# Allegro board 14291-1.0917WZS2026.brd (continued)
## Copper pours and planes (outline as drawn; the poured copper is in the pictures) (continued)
3D3V_S5_WLAN on BOTTOM: 167.41,40.5 167.15,40.76 167.15,45.3 167.26,45.41 169.18,45.41 169.62,44.97 169.62,40.72 169.4,40.5
3D3V_S5_WLAN on L4: 167.62,65.13 169.07,65.13 169.5,64.7 169.5,60.42 170.63,59.29 170.63,40.85 169.92,40.14 167.71,40.14 167.33,40.52 167.33,41.46 167.86,41.99 167.86,51.54 166.82,52.59 166.82,62.2 167.38,62.76 167.38,64.89
3D3V_TPM on BOTTOM: 167.8,18.62 167.63,18.8 167.63,19.33 168.04,19.74 168.04,20.99 168.16,21.11 169.23,21.11 169.52,21.4 172.66,21.4 172.8,21.26 172.8,20.81 172.66,20.68 171.5,20.68 171.35,20.52 171.35,19.68 170.66,19 168.9,19 168.53,18.62 ; 7 cut-outs
3D3V_TPM_1 on BOTTOM: 162.05,31.68 160.7,31.68 160.6,31.58 160.6,29.39 160.61,29.38 160.6,29.37 160.6,29.04 160.68,28.96 162.4,28.96 162.5,29.06 162.5,29.93 162.71,30.13 162.71,31.02
3D3V_VGA_S0 on TOP: 197.86,137.95 197.68,138.14 197.68,139.92 197.81,140.05 198.33,140.05 198.46,139.92 198.46,138.84 198.57,138.84 198.8,138.61 200.53,138.61 201.4,139.48 202.56,139.48 202.65,139.56 202.65,140.92 202.83,141.11 203.45,141.11 204.15,141.81 211.71,141.81 212.92,140.6 212.92,139.91 212.75,139.73 209.44,139.73 208.66,140.52 205.84,140.52 204.49,139.17 203.96,139.17 203.53,138.74 203.07,138.74 202.81,138.49 201.47,138.49 200.93,137.95 ; 4 cut-outs
3D3V_VGA_S0 on BOTTOM: 167.41,127.56 167.23,127.75 167.23,129.36 166.45,130.14 166.45,135.05 163.36,138.13 163.36,144.04 163.79,144.47 163.79,148.11 165.86,150.18 166.99,150.18 168.17,149 168.17,146.46 165.5,143.79 165.5,141.55 166.37,140.68 166.37,138.31 168.05,136.63 168.05,132.58 168.49,132.15 170.55,132.15 170.62,132.08 170.62,128.37 169.82,127.56 ; 2 cut-outs
3D3V_VGA_S0 on BOTTOM: 211.55,139.86 211.42,139.98 211.42,140.52 211.6,140.7 212.01,140.7 212.19,140.87 212.19,142.3 212.01,142.47 211.42,142.47 211.22,142.27 211.22,141.81 211.13,141.72 209.95,141.72 209.78,141.89 209.78,142.51 209.64,142.65 208.94,142.65 208.83,142.76 208.83,143.15 208.96,143.28 209.91,143.28 210.88,144.25 210.88,150.21 218.34,157.66 218.34,172.9 215,176.25 215,177.47 215.29,177.77 217.25,177.77 219.51,175.52 219.51,156.55 212.55,149.59 212.55,144.42 213.47,143.5 213.47,143.15 213.48,143.15 213.48,140.56 212.78,139.86 ; 4 cut-outs
3D3V_VGA_S0 on L3: 217.06,178.46 217.06,176.7 216.75,176.39 193.79,176.39 193.45,176.74 183.75,176.74 180.89,173.88 170.47,173.88 167.06,170.47 167.06,148.82 166.63,148.4 165.51,148.4 164.63,149.28 164.63,159.42 165.65,160.44 165.65,163.9 164.81,164.74 164.81,173.94 168.52,177.65 168.52,179.03 169.19,179.7 186.44,179.7 187.43,178.72 216.8,178.72
81208_AGND on BOTTOM: 115.98,140.78 115.55,141.22 114.32,141.22 114.32,141.22 110.68,141.22 110.46,141 110.05,141 110,141.05 110,141.48 110.08,141.56 110.48,141.56 110.76,141.84 110.76,141.84 110.85,141.93 111.25,141.93 111.41,142.09 111.41,145.16 111.59,145.34 116.2,145.34 116.38,145.53 117.08,145.53 117.15,145.45 117.15,144.98 116.99,144.82 116.99,143.43 116.93,143.37 116.77,143.37 116.63,143.22 116.63,141.74 117.01,141.36 117.22,141.36 117.29,141.28 117.29,140.82 117.25,140.78 116.47,140.78 116.46,140.78 ; 18 cut-outs
+0D675V_DDR_P on TOP: 44.47,21.54 44,22.01 43.58,22.01 43.52,21.94 41.25,21.94 40.92,22.27 40.92,23.82 40.99,23.89 44.27,23.89 45.03,24.66 46.11,24.66 46.73,24.03 46.73,23.02 46.68,22.97 45.86,22.97 45.86,23.18 45.66,23.18 45.53,23.3 44.98,23.3 44.7,23.02 44.7,22.64 44.98,22.36 46.73,22.36 46.73,22.17 45.25,22.17 44.61,21.54 ; 3 cut-outs
+DC_IN on TOP: 85.47,152.17 85.47,153.07 84.81,153.73 84.81,158.61 85.61,159.4 85.61,162.35 85.97,162.72 89.55,162.72 89.85,162.42 89.85,161.11 90.8,160.16 90.8,157.61 91.04,157.37 91.9,157.37 93.52,158.98 96.35,158.98 96.68,159.31 97.17,159.31 97.24,159.24 97.24,158.72 96.88,158.36 96.87,158.36 96.87,155.78 96.85,155.76 95.27,155.76 95.09,155.58 95.09,155.05 94.18,154.13 93.04,154.13 92.93,154.03 92.93,152.52 92.45,152.04 85.6,152.04 ; 1 cut-out
+DC_IN on BOTTOM: 88.95,151.89 88.71,152.12 88.71,154.97 88.11,155.58 88.11,156.75 88.87,157.51 90.46,157.51 91.19,158.25 91.19,159.31 91.35,159.47 94.68,159.47 95.77,158.38 95.77,155.59 96.01,155.35 96.01,153.17 95.52,152.68 93.19,152.68 92.41,151.89 ; 5 cut-outs
+DC_IN on L3: 88.54,152.43 91.23,152.43 92.45,153.65 94.66,153.65 95.24,154.23 95.24,158.81 94.48,159.57 89.15,159.57 87.29,157.71 87.29,153.67
+PWR_SRC_1D35V on TOP: 53.97,22.89 53.72,23.14 53.72,24.79 53.08,25.43 53.08,26.57 53.21,26.7 60.07,26.7 60.32,26.45 60.32,23.02 60.19,22.89 ; 2 cut-outs
+PWR_SRC_1D35V on BOTTOM: 52.61,22.89 52.17,23.34 52.17,26.86 52.31,27.01 56.86,27.01 57.73,26.14 57.73,22.99 57.63,22.89
+SDC_IN on TOP: 100.71,152.35 100.71,149.86 100.88,149.69 101.44,149.69 102.48,148.65 104.16,148.65 105,149.48 105,153.67 104.95,153.73 104.13,153.73 103.93,153.93 103.93,154.79 103.68,155.05 102.38,155.05 102.28,154.94 102.28,152.71 101.93,152.35
AD+ on TOP: 101.98,159.8 97.81,159.8 97.45,159.43 97.45,158.58 97.18,158.31 97.18,150.09 97.51,149.76 100.1,149.76 100.32,149.99 100.32,154.46 102.26,156.39 105.13,156.39 105.33,156.6 105.33,157.03 105.23,157.13 101.87,157.13 101.09,156.34 100.6,156.34 100.32,156.62 100.32,158.2 100.58,158.45 101.87,158.45 102.15,158.73 102.15,159.62
AUD_AGND on TOP: 23.25,9.05 23.08,9.21 23.08,9.38 22.91,9.55 21.9,9.55 21.74,9.72 21.74,10.49 21.86,10.61 22.96,10.61 23.06,10.71 23.06,11.33 23.19,11.46 23.97,11.46 24.34,11.1 24.34,10.38 24.12,10.16 24.12,9.15 24.02,9.05 ; 3 cut-outs
AUD_AGND on TOP: 28.09,23.15 28.04,23.2 28.04,23.43 27.62,23.86 26.02,23.86 25.65,23.49 24.94,23.49 24.81,23.49 24.71,23.59 24.71,24.02 24.54,24.19 24,24.19 23.81,24.38 23.81,25.56 24.17,25.91 28.82,25.91 29,25.73 29,23.88 28.73,23.61 28.73,23.22 28.66,23.15 ; 5 cut-outs
AUD_AGND on TOP: 19.86,16.77 19.81,16.82 19.81,18.62 19.17,19.26 18.13,19.26 18.05,19.33 18.05,20.22 18.36,20.53 18.36,21.37 18.41,21.42 19.07,21.42 19.2,21.54 19.2,21.95 19.35,22.1 20.49,22.1 20.85,21.75 22.48,21.75 22.73,21.5 22.73,20.91 22.61,20.79 21.7,20.79 21.31,21.19 20.11,21.19 19.96,21.04 19.96,20.22 20.06,20.12 20.54,20.12 20.72,19.94 20.72,16.9 20.59,16.77 ; 3 cut-outs
AUD_AGND on BOTTOM: 27.84,23.89 27.59,24.14 27.59,24.78 27.11,25.25 25.48,25.25 24.34,24.1 23.88,24.1 23.65,24.34 23.65,26.25 24.35,26.96 29.62,26.96 29.81,26.77 29.81,24.39 29.31,23.89 ; 3 cut-outs
AUD_AGND on L2VCC: outline of 84 points within 0.76,1.23 30.64,25.95
AUD_AGND on L5GND: outline of 84 points within 0.76,1.23 30.64,25.95
AUD_SPK_L+ on TOP: 39.3,13.14 39.18,13.27 39.18,14.47 39.37,14.66 39.67,14.66 40.05,14.28 40.81,14.28 40.88,14.34 41.71,14.34 41.75,14.3 41.75,13.4 41.68,13.32 39.79,13.32 39.61,13.14 ; 2 cut-outs
AUD_SPK_L+_C on TOP: 43.58,11.35 42.88,12.05 42.88,12.88 42.25,13.51 42.25,14.29 42.29,14.33 43.24,14.33 44.08,13.49 44.08,12.73 44.45,12.37 46.12,12.37 46.2,12.29 46.2,11.41 46.14,11.35 ; 1 cut-out
AUD_SPK_L+_C on TOP: 63.19,10.75 63.11,10.83 63.11,11.74 63.16,11.78 64.25,11.78 64.36,11.66 71.59,11.66 71.63,11.63 71.63,10.95 71.55,10.88 64.36,10.88 64.24,10.75
AUD_SPK_L- on TOP: 40.26,11.06 39.66,11.66 39.39,11.66 39.26,11.79 39.26,12.64 39.7,13.08 40.87,13.08 40.89,13.06 40.89,11.94 40.86,11.92 40.86,11.17 40.75,11.06 ; 1 cut-out
AUD_SPK_L-_C on TOP: 63.16,9.48 63.11,9.54 63.11,10.47 63.16,10.52 64.62,10.52 64.76,10.66 71.52,10.66 71.59,10.59 71.59,9.96 71.5,9.88 65.11,9.88 64.72,9.48
AUD_SPK_L-_C on TOP: 41.98,10.08 41.4,10.66 41.4,13.06 41.55,13.21 42.32,13.21 42.45,13.08 42.45,11.24 42.59,11.1 46.19,11.1 46.21,11.08 46.21,10.11 46.18,10.08
AUD_SPK_R+ on TOP: 37.5,8.89 37.26,9.13 37.26,9.82 37.43,9.99 39.73,9.99 39.85,9.87 39.85,8.98 39.77,8.89 ; 2 cut-outs
AUD_SPK_R+_C on TOP: 63.13,8.2 62.99,8.34 62.99,9.02 63.19,9.23 64.82,9.23 65.26,9.66 71.54,9.66 71.59,9.61 71.59,8.97 71.5,8.88 65.65,8.88 64.98,8.2
AUD_SPK_R+_C on TOP: 42.78,8.63 42.53,8.87 41.98,8.87 41.97,8.86 40.33,8.86 40.25,8.94 40.25,9.82 40.35,9.93 43.54,9.93 43.82,9.65 46.18,9.65 46.24,9.58 46.24,8.66 46.21,8.63
AUD_SPK_R- on TOP: 37.05,7.42 37,7.47 37,8.51 37.26,8.77 39.33,8.77 39.57,8.54 39.57,7.75 39.44,7.62 38.88,7.62 38.35,8.16 37.87,8.16 37.76,8.06 37.76,7.65 37.54,7.42
AUD_SPK_R-_C on TOP: 63.07,6.93 62.9,7.09 62.9,7.85 63,7.95 65.05,7.95 65.77,8.67 71.52,8.67 71.58,8.61 71.58,7.96 71.5,7.88 66.03,7.88 65.08,6.93
AUD_SPK_R-_C on TOP: 41.79,7.31 41.49,7.61 40.18,7.61 40.11,7.67 40.11,8.59 40.17,8.65 42.35,8.65 42.63,8.37 44.68,8.37 44.76,8.3 44.76,7.4 44.66,7.31
BT+ on TOP: 130.93,165.38 130.8,165.51 130.8,167.29 130.17,167.92 130.17,176.18 130.55,176.56 148.71,176.56 149.35,175.92 149.35,173.56 145.74,169.96 138.04,169.96 135,166.91 135,165.51 134.87,165.38 ; 2 cut-outs
BT+ on TOP: 159.76,171.23 159.38,171.61 159.38,177.42 159.18,177.63 159.18,180.98 159.33,181.13 163.82,181.13 164.08,180.88 164.08,178.85 163.29,178.06 163.29,175.57 164.08,174.78 164.08,171.35 163.95,171.23 ; 2 cut-outs
BT+ on BOTTOM: 131.06,167.16 130.17,168.05 130.17,177.07 130.55,177.45 157.86,177.45 159.13,178.72 159.13,180.88 159.38,181.13 163.7,181.13 164.08,180.75 164.08,172.37 161.79,170.08 154.05,170.08 151.94,167.97 143.48,167.97 141.54,169.91 137.39,169.91 134.65,167.16
CHARGER_SRC on TOP: 115.18,156.37 115.06,156.49 115.06,158.91 115.31,159.16 119.88,159.16 120.26,158.78 120.26,156.75 119.88,156.37 ; 2 cut-outs
CHARGER_SRC on BOTTOM: 120.26,155.48 119.88,155.86 114.93,155.86 113.91,156.87 113.91,159.03 114.04,159.16 123.31,159.16 123.44,159.03 123.44,155.73 123.18,155.48 ; 3 cut-outs
CHG_AGND on TOP: 106.17,159.29 105.66,159.8 105.66,162.39 106.49,163.22 107.51,163.22 107.57,163.16 107.57,162.25 107.82,162.01 107.82,159.8 107.31,159.29
CHG_AGND on L3: 106.4,165.51 105.65,164.77 100.42,164.77 100.27,164.62 100.27,156.8 101.47,155.6 102.53,155.6 103.37,156.44 112.59,156.44 112.77,156.62 112.77,157.05 112.31,157.51 109.52,157.51 107.79,159.24 107.79,168.36 108.12,168.69 108.12,170.03 107.89,170.25 106.69,170.25 106.4,169.96
CPVDD on TOP: 20.87,7.27 20.67,7.46 20.67,7.82 21,8.15 21,9.22 21.1,9.33 22.55,9.33 23.11,8.77 23.82,8.77 23.82,8.23 23.79,8.21 22.52,8.21 22.14,7.83 22.14,7.4 22.02,7.27 ; 3 cut-outs
DCBATOUT on TOP: 105.66,153.67 106.78,153.67 106.79,153.67 107.61,153.67 107.94,153.34 108.54,153.34 108.89,152.99 109.77,152.99 109.96,152.8 109.96,152.14 109.86,152.03 109.39,152.03 108.76,151.41 108.76,149.43 108.38,149.05 105.84,149.05 105.56,149.33 105.56,153.57
DCBATOUT on TOP: 138.84,156.22 140.09,156.22 140.36,155.95 140.36,153.6 140.64,153.33 140.64,152.54 140.52,152.42 139.65,152.42 139.26,152.03 137.81,152.03 136.95,152.89 136.95,155 137.1,155.16 137.78,155.16
DCBATOUT on TOP: outline of 102 points within 23.52,26.95 126.61,137.92
DCBATOUT on TOP: 101.34,149.41 99.05,149.41 98.93,149.28 98.93,148.37 99,148.29 101.16,148.29 101.52,148.65 101.52,149.23
DCBATOUT on TOP: 200.1,91.09 198.7,92.49 198.7,95.06 200.18,96.53 200.18,98.77 198.11,100.83 198.11,109.5 198.37,109.76 200.4,109.76 200.65,110.01 200.65,111.28 200.78,111.41 201.54,111.41 201.67,111.28 201.67,105.95 201.92,105.69 202.69,105.69 202.81,105.57 202.81,101.12 204.49,99.45 204.49,97.39 205.63,96.25 212.11,96.25 213.96,98.1 213.96,98.99 215.78,100.81 215.78,105.25 215.91,105.38 216.67,105.38 216.93,105.63 216.93,110.97 217.05,111.09 217.82,111.09 218.21,110.7 220.21,110.7 220.48,110.43 220.48,97.82 220.16,97.16 220.17,95.04 219.61,94.48 214.32,91.09 ; 1 cut-out
DCBATOUT on BOTTOM: 215.91,100.68 215.78,100.81 215.78,105.25 215.91,105.38 216.67,105.38 216.93,105.63 216.93,110.97 217.05,111.09 217.66,111.09 217.75,111 217.75,109.78 218.08,109.45 219.45,109.45 219.72,109.19 219.72,101.31 219.09,100.68 ; 2 cut-outs
DCBATOUT on BOTTOM: 99.35,118.51 99.07,118.79 99.07,135.99 99.5,136.42 99.5,142.18 98.14,143.54 98.14,147.17 98.15,147.18 98.15,148.18 98.66,148.7 98.66,152.37 99.24,152.96 110.4,152.96 112.12,154.68 112.12,155.69 112.53,156.1 114.41,156.1 115.06,155.45 119.71,155.45 120.44,154.72 132.7,154.72 134.33,153.09 136.29,153.09 136.65,153.45 136.65,156.62 136.77,156.75 140.33,156.75 140.71,156.37 140.71,150.14 140.93,149.93 140.93,149.51 142.83,147.6 144.67,147.6 145.66,146.61 145.66,139.6 145.41,139.35 140.96,139.35 140.2,138.59 140.2,135.28 139.95,135.03 137.97,135.03 137.59,135.41 137.59,139.43 136.82,140.19 131.59,140.19 130.94,139.54 130.31,139.54 129.36,138.59 129.36,135.13 128.02,133.79 125.12,133.79 124.07,132.74 124.07,130.71 123.95,130.59 121.91,130.59 121.79,130.71 121.79,136.26 121.53,136.52 119.03,136.52 117.82,135.31 117.82,134.03 117.35,133.55 111.43,133.55 111.07,133.19 111.07,131.23 110.77,130.93 110.77,130.13 110.74,130.1 108.32,130.1 108.13,130.28 108.13,135.52 107.88,135.77 104.1,135.77 103.82,135.49 103.82,119.16 103.17,118.51 ; 9 cut-outs
DCBATOUT on BOTTOM: 198.92,100.2 198.41,100.71 198.41,110.69 198.75,111.03 200.27,111.03 200.65,111.41 201.54,111.41 201.67,111.28 201.67,105.95 201.92,105.69 202.69,105.69 202.81,105.57 202.81,101.12 201.89,100.2 ; 2 cut-outs
DCBATOUT on L2VCC: 201.37,91.28 200.46,92.18 200.46,98.79 198.05,101.2 198.05,109.68 198.19,109.82 200.35,109.82 200.72,110.19 200.72,111.33 200.73,111.35 201.46,111.35 201.73,111.08 201.73,106 202.1,105.63 202.61,105.63 202.75,105.49 202.75,101.04 204.27,99.52 204.27,97.49 205.53,96.23 212.29,96.23 214.05,97.99 214.05,99.14 215.83,100.92 215.83,104.85 216.1,105.12 216.61,105.12 217.1,105.61 217.1,110.31 217.37,110.58 219.75,110.58 219.9,110.44 219.9,95.3 219.79,94.89 213.81,91.28
DCBATOUT on L2VCC: 99.77,118.58 99.37,118.98 99.37,138.25 99.9,138.78 107.87,138.78 108.75,137.89 124.76,137.89 125.74,136.91 125.74,132.93 124.58,131.77 109.11,131.77 107.21,129.87 107.21,120.25 105.54,118.58
DCBATOUT on L3: 200.33,100.59 200.01,100.27 196.77,100.27 192.29,104.75 190.6,104.75 180.38,114.97 180.38,115.71 179.3,116.79 171.3,116.79 155.77,132.31 155.77,138.52 148.55,145.74 139.78,145.74 136.24,149.28 136.24,156.6 136.42,156.78 141.44,156.78 141.55,156.67 141.55,152.57 142.1,152.03 152.22,152.03 164.66,139.58 164.66,138.75 168.04,135.37 168.04,131.19 175.16,124.07 175.16,123.37 176.55,121.98 182.86,121.98 187.09,117.75 188.12,117.75 190.58,115.29 192.75,115.29 195.65,112.39 195.65,107.23 196.23,106.65 198.1,106.65 200.33,104.42
DCBATOUT_+VCCSA on TOP: 135.25,131.98 135.12,132.11 135.12,133.89 135.25,134.01 137.92,134.01 138.1,133.83 138.1,132.21 137.88,131.99 137.58,131.99 137.58,131.98
DCBATOUT_+VCCSA on BOTTOM: 135.38,128.55 135.12,128.81 135.12,134.4 135.38,134.65 139.19,134.65 139.57,134.27 139.57,128.81 139.31,128.55 ; 2 cut-outs
DCBATOUT_CAMERA on TOP: 93.14,153.95 93.14,152.81 93.24,152.71 94.25,152.71 94.61,152.35 94.61,148.67 95.09,148.19 98.24,148.19 98.42,148.37 98.42,149.38 98.29,149.51 96.24,149.51 96.03,149.71 96.03,153.45 95.47,154 93.19,154
DCBATOUT_LCD on TOP: 76.69,176.67 76.56,176.8 76.56,177.34 76.69,177.48 78.54,177.48 78.58,177.43 78.58,176.73 78.52,176.67
DCBATOUT_LCD on BOTTOM: 91.49,150.15 92.28,150.15 94.47,152.34 96.81,152.34 96.87,152.28 96.87,148.85 96.14,148.12 96.14,147.18 95.87,146.91 91.7,146.91 91.33,147.27 91.33,150 ; 1 cut-out
DDR_VREF_S3 on TOP: 43.84,17.6 43.71,17.73 43.71,19.23 43.97,19.49 44.76,19.49 44.87,19.38 44.87,18.93 44.49,18.54 44.49,17.7 44.39,17.6
ECVBAT on TOP: 188.7,59.45 188.59,59.57 188.59,61.06 188.38,61.27 188.36,61.27 187.92,61.72 187.92,62.52 188.05,62.66 188.39,62.66 188.64,62.91 188.64,64.19 188.68,64.23 189.17,64.23 189.26,64.14 189.26,59.64 189.07,59.45
FAN_VCC1 on TOP: 99.03,141.56 98.19,141.56 96.64,140.01 94.81,140.01 94.71,139.91 94.71,137.72 96.49,135.95 96.49,135.13 96.77,134.85 97.33,134.85 97.48,135.01 97.48,138.56 97.89,138.97 98.45,138.97 98.57,139.09 98.57,140.47 98.75,140.64 98.98,140.64 99.11,140.77 99.11,141.48
FB_CAL_PD_VDDQ on TOP: 201.31,149.37 201.18,149.49 201.18,149.83 201.43,150.07 201.72,150.07 201.87,150.23 201.87,150.71 202,150.84 202.48,150.84 202.56,150.76 202.56,149.65 202.28,149.37
FB_CAL_PU_GND on TOP: 202.14,151.08 201.9,151.31 201.9,152.2 201.98,152.28 203.07,152.28 203.39,151.96 203.39,151.29 203.18,151.08 ; 1 cut-out
FB_CAL_TERM_GND on TOP: 204.08,153.09 203.89,153.28 203.89,153.67 204,153.78 204.36,153.78 204.54,153.96 204.54,154.54 204.6,154.6 205.33,154.6 205.43,154.5 205.43,153.55 204.96,153.09 ; 1 cut-out
FBA_PLL_AVDD on TOP: 188.01,143.85 187.9,143.95 187.9,146.01 188.08,146.18 188.08,147.52 188.29,147.73 192.43,147.73 192.68,147.98 192.68,148.32 192.48,148.52 192.22,148.52 192.08,148.67 192.08,149.1 192.19,149.21 194.21,149.21 194.3,149.12 194.3,148.66 194.1,148.47 193.82,148.47 193.59,148.24 193.59,148.04 192.6,147.05 192.26,147.05 191.73,146.51 190.93,146.51 190.47,146.05 189.71,146.05 188.95,145.29 188.95,143.94 188.85,143.85 ; 3 cut-outs
FBA_PLL_AVDD on L3: 192.11,149.39 194.1,149.39 194.2,149.3 194.2,148.6 194.3,148.51 197.04,148.51 197.08,148.55 197.08,148.54 197.48,148.54 197.73,148.8 197.73,149 197.94,149.2 198.26,149.2 198.65,148.82 198.65,146.23 199.28,145.6 199.28,143.74 199.17,143.64 198.6,143.64 198.47,143.77 198.47,144.63 196.19,146.91 194.34,146.91 193.75,147.5 191.99,147.5 191.76,147.73 191.76,148.47 191.96,148.66 191.96,149.24
HDMI_PLL_GND on TOP: 19.07,60.42 19.02,60.46 19.02,68.52 19.73,69.23 19.73,69.24 22.73,69.24 22.88,69.09 22.88,68.23 22.73,68.08 22.12,68.08 21.84,68.36 20.87,68.36 20.87,68.1 20.26,67.49 20.26,60.46 20.22,60.42 ; 2 cut-outs
KB_BL_CTRL# on TOP: 193.94,96.16 193.89,96.21 193.89,97.3 193.99,97.4 194.66,97.4 194.75,97.31 194.75,96.2 194.71,96.16
LCDVDD on BOTTOM: 79.52,157.52 79.43,157.61 79.43,160.4 79.57,160.54 81.26,160.54 81.4,160.4 81.4,157.68 81.24,157.52
LCDVDD_LCD on TOP: 77.66,174.16 77.6,174.23 77.6,175.9 77.67,175.98 78.63,175.98 79.22,176.57 81.46,176.57 81.66,176.37 81.66,175.58 81.5,175.41 79.77,175.41 78.51,174.16
LCDVDD_LCD on BOTTOM: 82.11,158.71 81.87,158.94 81.87,161.19 81.53,161.52 79.84,161.52 79.39,161.97 79.39,175.26 78.99,175.66 78.99,177.12 79.33,177.46 81.37,177.46 82.35,176.49 82.35,168.73 83.91,167.17 83.91,158.92 83.69,158.71 ; 3 cut-outs
M_VREF_CA_DIMMA on TOP: 102.71,27.3 102.44,27.57 102.44,28.83 103.03,29.42 105.32,29.42 105.59,29.14 105.59,27.66 105.23,27.3 ; 3 cut-outs
M_VREF_CA_DIMMA on BOTTOM: 102.71,27.29 102.42,27.59 102.42,27.97 102.92,28.47 102.92,28.48 102.99,28.55 102.99,30.64 103.02,30.66 103.27,30.66 103.3,30.64 103.3,28.94 103.63,28.6 103.63,27.77 103.16,27.29
M_VREF_CA_DIMMB on TOP: 117.05,17.89 116.85,18.08 116.85,19.24 116.67,19.42 116.67,21.29 116.88,21.5 117.42,21.5 117.52,21.39 117.52,19.08 118.13,18.47 118.13,17.99 118.03,17.89
M_VREF_DQ_DIMMA on TOP: 59.2,38.31 58.95,38.56 58.95,39.88 59.54,40.47 59.99,40.47 61.13,39.32 62.55,39.32 62.78,39.08 62.78,38.42 62.67,38.31 ; 3 cut-outs
M_VREF_DQ_DIMMA on TOP: 56.2,45.5 55.88,45.82 55.88,47.09 55.72,47.25 55.23,47.25 55.08,47.4 55.08,47.92 55.21,48.06 56.55,48.06 56.68,47.92 56.68,46.48 56.85,46.31 57.49,46.31 57.58,46.23 57.58,45.6 57.48,45.5 ; 1 cut-out
M_VREF_DQ_DIMMA on BOTTOM: 62.54,37.29 62.07,37.76 62.07,38.85 62.33,39.12 63.33,39.12 63.39,39.06 63.39,37.39 63.29,37.29
M_VREF_DQ_DIMMB on TOP: 77.46,23.53 77.46,23.54 77.12,23.54 77.01,23.65 77.01,26.71 77.21,26.91 77.93,26.91 78.12,26.72 78.12,24.95 78.1,24.94 78.1,23.64 78,23.53 ; 2 cut-outs
M_VREF_DQ_DIMMB on TOP: 58.77,35.47 58.58,35.66 58.58,36.47 58.71,36.6 61.17,36.6 61.24,36.53 61.24,35.62 61.1,35.47
M_VREF_DQ_DIMMB on BOTTOM: 77.09,23.99 76.89,24.19 76.89,25.88 76.62,26.15 76.32,26.15 76.19,26.28 76.19,27.2 76.25,27.26 77.58,27.26 77.92,26.92 77.92,24.11 77.79,23.99
MCT on TOP: 18.66,170.97 18.54,171.1 18.54,173.77 18.79,174.02 21.97,174.02 22.22,173.77 22.22,171.23 21.97,170.97
MIC_GND on BOTTOM: 78.05,164.44 77.84,164.65 77.84,166.16 78.09,166.41 79.01,166.41 79.32,166.1 79.32,164.74 79.02,164.44 ; 1 cut-out
PQ3802_1 on TOP: 104.66,173.25 104.58,173.33 104.58,173.75 104.78,173.95 109.51,173.95 110.85,175.29 113.41,175.29 113.53,175.16 113.53,174.02 113.28,173.77 110.96,173.77 110.44,173.25 ; 2 cut-outs
PS_ID_R1 on TOP: 104.37,175.92 104.18,176.1 104.18,177.28 104.42,177.52 107.13,177.52 107.23,177.41 107.23,176.24 106.91,175.92 ; 2 cut-outs
PS_ID_R2 on TOP: 101.7,172.56 101.61,172.65 101.61,175.42 101.82,175.63 104.6,175.63 104.6,175.63 108.14,175.63 108.26,175.5 108.26,174.52 108.02,174.28 104.54,174.28 104.32,174.06 104.32,173.44 103.44,172.56 ; 4 cut-outs
PSID_DISABLE#_R_C on TOP: 111.78,175.52 111.67,175.63 111.67,176.14 111.51,176.31 108.54,176.31 108.37,176.48 108.37,177.37 108.51,177.52 114.08,177.52 114.55,177.05 114.55,176.14 113.93,175.52 ; 1 cut-out
PWR_1D0V_BOOT on TOP: 146.63,136.95 146.48,137.11 146.48,137.63 146.63,137.78 148.73,137.78 148.81,137.7 148.81,137.09 148.67,136.95
PWR_1D0V_BOOT_R on TOP: 146.7,134.28 146.55,134.43 146.55,136.42 146.63,136.5 148.31,136.5 148.52,136.29 148.52,134.41 148.39,134.28 ; 1 cut-out
PWR_1D0V_LX on TOP: 145.52,133.35 145.31,133.56 145.31,133.59 144.44,134.46 144.44,135.26 144.57,135.4 146.11,135.4 146.21,135.29 146.21,134.15 146.56,133.8 146.56,133.49 146.41,133.35 ; 1 cut-out
PWR_1D0V_LX on BOTTOM: 144.01,130.46 143.76,130.71 143.76,133.25 144.01,133.51 145.66,133.51 145.79,133.63 145.79,134.9 145.92,135.03 146.93,135.03 147.06,134.9 147.06,133.76 147.19,133.63 147.95,133.63 148.08,133.51 148.08,130.59 147.95,130.46
PWR_1D05V_PHASE on BOTTOM: 149.09,153.45 148.46,154.08 147.31,154.08 147.19,154.21 147.19,156.73 147.55,157.1 150.65,157.1 151.25,156.49 151.25,153.57 151.12,153.45
PWR_1D05V_PVDD on BOTTOM: 141.35,154.33 141.22,154.46 141.22,158.65 141.35,158.78 144.52,158.78 144.77,158.53 144.77,156.24 145.03,155.99 145.03,154.72 144.9,154.59 143.38,154.59 142.87,155.1 141.98,155.1 141.85,154.97 141.85,154.46 141.73,154.33 ; 2 cut-outs
PWR_1D35V_DRVH on TOP: 62.42,25.07 61.93,25.56 60.7,25.56 60.7,26.19 60.83,26.32 62.72,26.32 63.46,25.58 63.46,25.22 63.3,25.07
PWR_1D35V_DRVL on TOP: 57.7,17.49 57.53,17.67 57.53,19.46 58.54,19.46 58.67,19.33 58.67,17.66 58.5,17.49
PWR_1D35V_SW on TOP: 60.83,15.9 60.7,16.03 60.7,17.68 60.57,17.81 59.3,17.81 59.05,18.06 59.05,22.25 59.18,22.38 60.45,22.38 60.7,22.64 60.7,25.3 61.88,25.3 62.29,24.89 63.44,24.89 63.62,24.71 63.62,17.17 63.43,16.99 62.04,16.99 61.75,16.7 61.75,16 61.66,15.9
PWR_1D35V_SW on BOTTOM: 60.07,17.05 59.05,18.06 59.05,18.08 58.91,18.22 58.91,24.65 59.13,24.87 63.27,24.87 63.62,24.52 63.62,17.17 63.49,17.05
PWR_1D35V_VTTREF on TOP: 45.09,17.56 45.02,17.63 45.02,19.68 44.89,19.81 44.89,20.69 45.46,21.27 45.46,21.49 45.52,21.55 46.76,21.55 46.76,20.76 45.9,19.9 45.9,19.54 45.89,19.53 45.89,17.66 45.79,17.56
PWR_3D3V_DRVH2 on TOP: 31.01,41.17 30.88,41.3 30.88,43.08 31.01,43.2 31.52,43.2 31.64,43.08 31.64,41.3 31.52,41.17
PWR_3D3V_DRVL2 on TOP: 33.29,45.23 33.17,45.36 33.17,47.14 33.29,47.27 33.8,47.27 33.93,47.14 33.93,45.36 33.8,45.23
PWR_3D3V_LL2 on TOP: 29.76,39.24 27.89,41.1 27.89,42.99 28.1,43.2 30.63,43.2 30.63,41.04 30.75,40.92 31.9,40.92 32.28,41.3 32.28,44.85 32.41,44.98 36.72,44.98 36.85,44.85 36.85,41.46 36.92,41.4 38.61,41.4 38.81,41.19 38.81,40.06 38.67,39.93 32.96,39.93 32.27,39.24
PWR_3D3V_LL2 on BOTTOM: 28.9,40 28.72,40.18 28.72,44.6 29.1,44.98 36.72,44.98 36.85,44.85 36.85,40.76 36.09,40
PWR_5V_DRVH1 on TOP: 48.38,41.18 48.25,41.3 48.25,43.08 48.38,43.21 49.02,43.21 49.14,43.08 49.14,41.43 48.89,41.18
PWR_5V_DRVL1 on TOP: 40.91,45.23 40.79,45.36 40.79,46.25 40.91,46.38 42.18,46.38 42.18,45.36 42.06,45.23
PWR_5V_LL1 on TOP: 39.17,40.15 39.06,40.26 39.06,41.17 39.28,41.38 40.73,41.38 41.04,41.69 41.04,44.73 41.17,44.85 45.23,44.85 45.36,44.73 45.36,43.46 45.61,43.2 47.9,43.2 48.03,43.08 48.03,40.28 47.9,40.15
PWR_5V_LL1 on BOTTOM: 41.9,40.13 41.3,40.74 41.3,44.35 41.68,44.73 47.39,44.73 47.9,44.22 47.9,40.41 47.62,40.13
PWR_+VCCSA on BOTTOM: 133.98,116.62 133.09,117.5 133.09,120.3 133.34,120.55 138.93,120.55 139.31,120.17 139.31,116.74 139.19,116.62
PWR_CHG_HIDRV on BOTTOM: 123.82,155.86 123.69,155.99 123.69,156.62 125.72,156.62 125.85,156.49 125.85,155.99 125.72,155.86
PWR_CHG_LODRV on BOTTOM: 120.52,162.84 120.39,162.97 120.39,163.99 120.52,164.11 121.53,164.11 121.66,163.99 121.66,162.97 121.53,162.84
PWR_CHG_PHASE on BOTTOM: 126.87,156.24 126.23,156.87 123.82,156.87 123.69,157 123.69,159.16 123.44,159.41 122.17,159.41 121.91,159.67 121.91,163.86 122.52,164.47 128.19,164.47 128.9,163.76 128.9,156.62 128.52,156.24
PWR_CHG_PHASE_1 on TOP: 131.19,157.13 130.8,157.51 130.8,164.62 131.06,164.88 134.87,164.88 138.97,160.78 138.97,158.95 137.51,157.49 136.18,157.49 135.82,157.13
PWR_CHG_PHASE_1 on BOTTOM: 131.19,157.13 130.8,157.51 130.8,164.62 131.06,164.88 134.87,164.88 139.31,160.43 139.31,157.38 139.06,157.13
PWR_DCBATOUT_1D0V on BOTTOM: 144.9,136.05 144.52,136.43 140.84,136.43 140.71,136.55 140.71,138.59 141.22,139.09 146.81,139.09 147.01,138.89 147.01,136.12 146.93,136.05
PWR_DCBATOUT_3D3V on TOP: 28.47,43.46 27.81,44.12 27.81,50.4 27.85,50.44 32.02,50.44 32.15,50.31 32.15,43.71 31.9,43.46 ; 2 cut-outs
PWR_DCBATOUT_3D3V on BOTTOM: 28.36,47.14 27.98,47.52 27.98,50.31 28.1,50.44 32.15,50.44 32.28,50.31 32.28,47.39 32.02,47.14
PWR_DCBATOUT_5V on TOP: 45.87,43.46 45.61,43.71 45.61,46.89 45.36,47.14 45.36,51.2 45.74,51.58 49.42,51.58 49.42,43.58 49.3,43.46 ; 2 cut-outs
PWR_DCBATOUT_5V on BOTTOM: 45.87,46.5 45.61,46.76 45.61,47.9 45.36,48.16 45.36,50.06 45.49,50.19 47.14,50.19 48.15,49.17 48.15,46.76 47.9,46.5
PWR_VCCGT_BOOTA on BOTTOM: 112.59,130.1 112.57,130.13 112.57,133.04 112.72,133.19 113.25,133.19 113.46,132.99 113.46,131.45 112.77,130.76 112.77,130.15 112.72,130.1
PWR_VCCGT_GL1 on BOTTOM: 111.48,126.14 111.37,126.24 111.37,126.95 111.42,127 112.72,127 112.77,126.95 112.77,126.22 112.69,126.14
PWR_VCCGT_PHASEDA on BOTTOM: 111.4,130.1 111.37,130.13 111.37,133.01 111.57,133.2 112.14,133.2 112.36,132.98 112.36,130.13 112.34,130.1 112.19,130.1 112.16,130.13 112.16,130.81 112.14,130.84 111.6,130.84 111.55,130.79 111.55,130.13 111.53,130.1
PWR_VCCGT_SWA on BOTTOM: 111.63,122 111.4,122.23 110.36,122.23 110.23,122.1 107.92,122.1 107.69,122.33 107.69,126.7 107.94,126.95 111.12,126.95 111.17,126.9 111.17,126.22 111.5,125.89 112.26,125.89 112.77,125.38 112.77,122.18 112.59,122
PWR_VCCSA_DRVH on BOTTOM: 135.25,127.03 135.12,127.16 135.12,128.05 135.25,128.17 136.39,128.17 136.39,127.03
PWR_VCCSA_DRVL on BOTTOM: 133.47,130.2 133.34,130.33 133.34,132.11 133.47,132.24 133.98,132.24 134.11,132.11 134.11,130.33 133.98,130.2
PWR_VCCSA_SW on BOTTOM: 132.89,123.09 130.8,125.18 130.8,129.7 130.93,129.82 134.49,129.82 134.74,129.57 134.74,127.03 135,126.78 136.52,126.78 136.65,126.9 136.65,128.05 136.77,128.17 138.3,128.17 138.42,128.05 138.42,123.35 138.17,123.09
PWR_VCORE_BOOT on BOTTOM: 125.93,130.61 125.9,130.64 125.9,133.64 126.01,133.75 126.68,133.75 126.79,133.64 126.79,131.91 126.11,131.22 126.11,130.66 126.06,130.61
PWR_VCORE_GL on BOTTOM: 124.81,126.65 124.71,126.75 124.71,127.46 124.76,127.51 126.06,127.51 126.11,127.46 126.11,126.73 126.03,126.65
PWR_VCORE_PHASED on BOTTOM: 124.73,130.61 124.71,130.64 124.71,133.24 125.22,133.75 125.56,133.75 125.7,133.62 125.7,130.64 125.67,130.61 125.52,130.61 125.5,130.64 125.5,131.32 125.47,131.35 124.96,131.35 124.89,131.27 124.89,130.64 124.86,130.61
PWR_VCORE_SW on BOTTOM: 120.98,122.86 120.8,123.04 120.8,127.13 121.13,127.46 124.45,127.46 124.51,127.41 124.51,126.73 124.84,126.39 125.17,126.39 125.56,126 125.56,123.05 125.37,122.86
PWR_VGA_CORE_LGATE1 on TOP: 212.21,105.19 212.08,105.31 212.08,106.84 212.21,106.96 213.1,106.96 213.23,106.84 213.23,105.31 213.1,105.19
PWR_VGA_CORE_LGATE1 on BOTTOM: 212.21,109.88 212.08,110.01 212.08,111.41 212.34,111.66 212.97,111.66 213.23,111.41 213.23,110.01 213.1,109.88
PWR_VGA_CORE_LGATE2 on TOP: 205.61,110.27 205.48,110.39 205.48,111.79 205.61,111.92 206.24,111.92 206.5,111.66 206.5,110.39 206.37,110.27
PWR_VGA_CORE_LGATE2 on BOTTOM: 205.61,105.57 205.48,105.69 205.48,107.09 205.61,107.22 206.37,107.22 206.5,107.09 206.5,105.82 206.24,105.57
PWR_VGA_CORE_PHASE1 on TOP, BOTTOM: 213.61,105.69 213.48,105.82 213.48,111.92 213.1,112.3 209.67,112.3 209.54,112.42 209.54,113.31 212.21,115.98 217.55,115.98 218.56,114.96 218.56,112.3 218.18,111.92 217.29,111.92 216.53,111.15 216.53,105.82 216.4,105.69
PWR_VGA_CORE_PHASE2 on TOP, BOTTOM: 202.18,105.95 202.05,106.07 202.05,111.41 201.67,111.79 201.04,111.79 200.27,112.55 200.27,115.47 200.91,116.11 206.37,116.11 209.29,113.19 209.29,112.3 209.16,112.17 207.77,112.17 207.39,112.55 205.73,112.55 205.23,112.04 205.23,106.33 204.85,105.95
PWR_VGA_CORE_UGATE1 on TOP: 218.31,105.19 218.18,105.31 218.18,106.84 218.31,106.96 219.2,106.96 219.32,106.84 219.32,105.44 219.07,105.19
PWR_VGA_CORE_UGATE1 on BOTTOM: 218.31,109.88 218.18,110.01 218.18,111.54 218.31,111.66 219.07,111.66 219.2,111.54 219.2,110.01 219.07,109.88
PWR_VGA_CORE_UGATE2 on TOP: 199.51,110.27 199.38,110.39 199.38,111.79 199.51,111.92 200.27,111.92 200.4,111.79 200.4,110.39 200.27,110.27
PWR_VGA_CORE_UGATE2 on BOTTOM: 199.51,105.57 199.38,105.69 199.38,107.09 199.51,107.22 200.27,107.22 200.4,107.09 200.4,105.69 200.27,105.57
REGOUT on TOP: 48.2,170.27 48.17,170.3 48.17,171.54 49.29,172.65 50.61,172.65 50.95,172.31 51.48,172.31 51.57,172.22 51.57,171.35 51.43,171.21 50,171.21 49.98,171.2 49.05,170.27 ; 3 cut-outs
RING2 on TOP: 16.56,9.35 15.07,10.84 15.07,11.89 15.22,12.04 16,12.04 16.52,11.52 16.52,10.92 16.8,10.64 17.33,10.64 17.52,10.45 17.52,9.47 17.4,9.35 ; 3 cut-outs
RING2_HPMIC1 on TOP: 16.34,8.02 15.68,8.69 14.25,8.69 14.04,8.9 14.04,9.89 14.16,10.01 15.71,10.01 16.52,9.2 17.6,9.2 17.6,8.15 17.47,8.02 ; 1 cut-out
RTC_AUX_S5 on TOP: 134.44,56.71 134.34,56.81 134.34,58.92 134.54,59.12 136.15,59.12 136.15,59.12 136.35,59.12 136.71,58.75 136.71,56.78 136.64,56.71 ; 2 cut-outs
SD_RCOMP on TOP: 134.69,83.99 134.4,84.28 134.4,84.43 135.77,85.8 139.23,85.8 139.33,85.69 140.23,85.69 140.3,85.63 140.3,85.19 140.22,85.11 136.49,85.11 136.39,85.21 136.18,85.21 134.96,83.99
SLEEVE on BOTTOM: 19.79,9.87 19.62,10.04 19.62,10.37 19.84,10.58 20.54,10.58 20.73,10.77 20.92,10.77 21.08,10.62 21.08,10.5 20.44,9.87
SLEEVE_HPMIC1 on TOP: 18.06,9 17.62,9.43 17.62,11.63 17.81,11.81 19.4,11.81 19.54,11.68 19.54,10.71 19.26,10.42 19.26,9.05 19.21,9 ; 1 cut-out
SM_RCOMP_0 on TOP: 123.08,73.26 123.01,73.33 123.01,73.92 123.82,74.73 123.82,76.22 125.12,77.51 126.33,77.51 126.41,77.43 126.41,77.02 126.34,76.96 125.16,76.96 124.3,76.1 124.3,74.43 123.72,73.84 123.72,73.39 123.59,73.26
SM_RCOMP_1 on TOP: 124.07,73.23 123.97,73.33 123.97,73.99 124.35,74.38 124.35,76.08 125.14,76.86 125.5,76.86 125.57,76.79 125.57,76.38 125.45,76.26 125.12,76.26 124.94,76.08 124.94,74.1 124.66,73.82 124.66,73.33 124.56,73.23
SM_RCOMP_2 on TOP: 124.89,73.26 124.84,73.31 124.84,73.87 125.01,74.05 125.01,75.99 125.18,76.15 125.42,76.15 125.55,76.03 125.55,75.7 125.42,75.57 125.42,74.78 125.47,74.73 125.47,73.33 125.39,73.26
SP_PLLVDD on TOP: 193.34,130.71 193.26,130.79 193.26,131.96 192.93,132.29 192.93,135.74 193.09,135.89 194.15,135.89 194.28,135.77 194.28,133.81 194.03,133.56 194.03,132.41 194.58,131.86 194.99,131.86 195.12,131.73 195.12,130.81 195.02,130.71 ; 4 cut-outs
TP_VDD on TOP: 54.02,69.4 53.8,69.62 53.8,70.85 53.85,70.89 53.85,71.33 53.92,71.4 55.31,71.4 55.42,71.3 55.42,69.44 55.38,69.4
TP_VDD on TOP: 47.72,76.23 47.68,76.27 47.68,76.49 47.13,77.03 47.13,79.96 47.57,80.4 49.61,80.4 49.88,80.13 49.88,78.99 48.65,78.99 48.29,78.64 48.29,76.98 48.1,76.8 48.1,76.39 48.11,76.39 48.11,76.28 48.06,76.23
TPAN_VDD on BOTTOM: 68.74,156.4 67.57,157.58 67.57,158.65 67.77,158.85 73.18,158.85 73.35,158.68 74.34,158.68 74.34,158.68 74.46,158.56 74.46,157.52 74.28,157.34 73.2,157.34 72.26,156.4 ; 1 cut-out
TPAN_VDD_F on BOTTOM: 73.61,159.09 72.33,160.36 69.21,160.36 68.9,160.67 68.9,162.43 70.26,163.78 72.61,163.78 73.59,162.81 73.59,160.55 73.95,160.19 77.02,160.19 77.25,159.96 77.25,159.22 77.11,159.09 ; 1 cut-out
TPS51216_PHS_SET on TOP: 57.8,15.9 57.4,16.3 57.4,17.3 57.45,17.35 59.08,17.35 59.14,17.41 60.08,17.41 60.08,15.9 ; 2 cut-outs
USB20_VCCA on TOP: 183.87,34.42 183.62,34.67 182.59,34.67 181.31,35.96 179.83,35.96 179.59,36.2 179.59,39.67 179.93,40.02 182.17,40.02 183.55,38.65 185.2,38.65 185.83,38.02 187.65,38.02 187.72,37.95 187.72,34.55 187.59,34.42
USB20_VCCA on BOTTOM: 180.21,28.14 179.94,28.41 179.94,28.96 180.05,29.07 180.05,29.06 181.2,29.06 181.76,29.62 182.42,29.62 182.58,29.47 182.58,28.26 182.45,28.14 ; 1 cut-out
USB20_VCCA on BOTTOM: 184.12,37.71 183.86,37.97 180.48,37.97 180.3,38.16 180.3,39.92 180.53,40.15 182.92,40.15 183.73,39.34 183.73,39.33 185.95,39.33 186.17,39.11 186.17,38.29 186.01,38.14 185.48,38.14 185.04,37.71 ; 2 cut-outs
USB20_VCCA on L4: 180.49,39.87 181.72,39.87 182.2,39.4 182.2,35.81 182.56,35.44 182.56,29.04 182.38,28.85 181.59,28.85 181.31,29.12 181.31,31.74 180.8,32.26 180.8,34.2 180.29,34.71 180.29,39.67
USB30_VCCB on TOP: 11.82,26.98 11.29,27.52 11.29,29.26 11.67,29.64 12.68,29.64 13.16,30.12 13.16,34.65 13.52,35.01 16.78,35.01 16.92,35.14 16.92,36.05 17.11,36.25 21.86,36.25 21.86,35.03 22.35,34.54 22.35,33.79 20.65,33.79 20.38,34.06 19.11,34.06 18.89,33.83 18.89,32.34 15.41,32.34 15.26,32.19 15.26,30.4 15.2,30.35 15.18,30.35 15.18,27.94 14.22,26.98 ; 4 cut-outs
USB30_VCCC on TOP: 16.47,38.22 16.4,38.29 16.4,41.53 15.83,42.11 15.83,43.5 15.46,43.87 14.07,43.87 13.9,44.04 13.9,45.29 14.24,45.64 16.99,45.64 17.47,45.15 17.47,43.08 17.67,42.88 18.46,42.88 18.64,43.06 22.35,43.06 22.45,43.16 22.45,44.33 22.52,44.4 23.78,44.4 23.91,44.26 23.91,42.05 23.83,41.98 23.83,41.84 23.59,41.59 23.59,40.78 23.53,40.72 21.53,40.72 21.46,40.8 21.46,40.82 21.38,40.9 18.38,40.9 18.38,39.85 18.88,39.85 19.01,39.72 19.02,39.72 19.02,38.57 18.68,38.23 18.68,38.22 ; 4 cut-outs
USB30_VCCC on BOTTOM: 15.34,44.86 15.34,44.89 15.29,44.94 14.32,44.94 14.14,45.11 14.14,46.13 12.47,47.81 11.86,47.81 11.42,48.24 11.42,49.76 11.82,50.16 13.09,50.16 16.99,46.26 17.17,46.26 17.17,44.94 17.09,44.86
USB30_VCCC on BOTTOM: 17.4,38.61 17.29,38.72 17.29,39.19 17.41,39.3 18.47,39.3 18.47,39.82 18.95,39.82 18.95,39.78 19.03,39.7 19.03,38.61
VGA_CORE on TOP: 207.51,117.38 207,117.89 202.69,117.89 202.18,118.39 202.18,122.97 203.07,123.85 207.39,123.85 208.66,125.12 208.66,125.38 212.72,129.44 215.51,129.44 216.02,128.93 216.02,121.95 217.55,120.43 217.55,117.76 217.16,117.38
VGA_CORE on TOP: 189.83,137.29 188.13,138.99 188.13,143.25 188.55,143.67 193.57,143.67 193.67,143.57 195.91,143.57 196.18,143.29 196.18,142.71 196.05,142.57 191.1,142.57 190.83,142.31 190.83,141.75 191.15,141.43 191.41,141.43 191.53,141.32 191.53,141.31 191.62,141.23 192.81,141.23 193.09,141.51 193.43,141.51 193.74,141.2 194.8,141.2 195.09,141.49 195.57,141.49 195.73,141.33 195.73,141.17 194.83,140.27 193.69,140.27 193.4,140.55 193.11,140.55 192.8,140.25 191.99,140.25 191.56,140.68 191.22,140.68 191.1,140.79 189.81,140.79 189.56,140.54 189.56,139.88 189.78,139.65 191.11,139.65 191.95,138.81 192.94,138.81 193.09,138.66 194.84,138.66 195.02,138.84 195.02,139.27 195.17,139.43 196.72,139.43 196.9,139.25 196.9,138.18 196.08,137.37 195.55,137.37 195.24,137.67 193.87,137.67 193.49,137.29 ; 7 cut-outs
VGA_CORE on TOP: 189.33,144.69 189.07,144.94 189.07,145.24 189.69,145.86 192.89,145.86 193.03,145.72 193.38,145.72 193.67,146.01 193.67,146.21 193.67,146.23 192.91,146.99 192.91,147.22 193.28,147.6 194.36,147.6 194.54,147.42 194.54,146.25 194.99,145.8 195.47,145.8 195.65,145.98 195.65,146.26 195.85,146.46 196.34,146.46 196.51,146.28 196.51,146.08 196.2,145.76 196.2,144.9 195.98,144.69 ; 7 cut-outs
VGA_CORE on BOTTOM: 202.18,117.5 201.67,118.01 201.67,120.68 202.69,121.7 202.69,125.77 203.13,126.21 208.93,126.21 209.9,127.18 209.9,127.64 210.81,128.55 210.81,133 214.12,136.3 214.12,137.7 214.5,138.08 217.67,138.08 217.8,137.95 217.8,133.38 216.15,131.73 216.15,122.07 218.27,119.95 218.27,117.81 217.96,117.5 ; 9 cut-outs
VGA_CORE on BOTTOM: 188.55,137.38 187.91,138.02 187.91,146.4 189.06,147.54 189.44,147.54 189.69,147.29 189.69,147.16 188.3,145.76 188.3,145.64 188.68,145.26 188.93,145.26 190.84,147.16 190.85,147.16 191.06,147.38 191.28,147.38 191.46,147.2 191.46,146.9 188.3,143.73 188.3,143.48 188.55,143.22 188.93,143.22 193.06,147.35 193.26,147.35 193.44,147.17 193.44,146.85 188.42,141.83 188.42,141.45 188.55,141.32 188.93,141.32 194.65,147.03 194.9,147.03 195.15,146.78 195.15,146.65 188.42,139.92 188.42,139.41 188.55,139.29 188.93,139.29 196.61,146.97 196.89,146.97 197.05,146.81 197.05,146.52 189.31,138.78 189.31,138.52 189.57,138.27 189.82,138.27 196.68,145.13 197.06,145.13 197.19,145 197.19,144.62 191.22,138.65 191.09,138.65 190.84,138.4 190.84,138.14 191.09,137.89 191.47,137.89 196.8,143.22 197.06,143.22 197.31,142.97 197.31,142.84 192.99,138.52 192.99,138.14 193.12,138.02 193.63,138.02 196.8,141.19 196.93,141.19 197.19,140.94 197.19,140.68 194.9,138.4 194.9,138.02 195.03,137.89 195.53,137.89 196.68,139.03 196.93,139.03 197.19,138.78 197.19,138.52 196.04,137.38
VGA_CORE on L2VCC: 207.46,117.19 206.96,117.7 199.21,117.7 198.43,118.47 198.43,121.52 187.64,132.32 187.64,145.87 188.29,146.52 198.16,146.52 199.07,145.62 199.07,143.67 199.44,143.3 202.73,143.3 202.94,143.1 210.86,143.1 216.09,137.87 216.09,122 217.61,120.47 217.61,117.58 217.21,117.19
VGA_CORE on L3: 187.53,134.18 188.13,134.78 188.13,147.27 188.56,147.71 191.46,147.71 191.87,147.3 193.62,147.3 194.16,146.76 196.14,146.76 196.92,145.98 196.92,137.39 196.11,136.58 196.11,136.28 196.36,136.02 197.78,136.02 201.28,132.53 202.8,132.53 204.87,130.46 206.4,130.46 207.18,129.67 215.14,129.67 216.45,128.36 216.45,121.7 217.55,120.6 217.55,117.63 217.16,117.25 207.51,117.25 207,117.76 192.3,117.76 187.53,122.53
VGA_CORE on L4: 188.32,136.64 188.32,133.11 193.02,128.41 194.7,128.41 197,126.12 197,119.89 198.37,118.52 198.5,118.52 199.38,117.63 207,117.63 207.39,117.25 217.16,117.25 217.55,117.63 217.55,120.73 216.45,121.82 216.45,135.1 215.57,135.98 213.99,135.98 213.66,135.65 213.24,135.65 212.65,135.07 207.66,135.07 205.64,137.1 202.86,137.1 202.46,136.7 200.85,136.7 198.12,139.43 191.1,139.43

Small or netless copper shapes (teardrops, artwork), in the pictures only: 2 on TOP, 5 on BOTTOM

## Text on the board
Ref Des/Silkscreen Bottom: F5701:1.1A/6V | F5502:1.1A/24V | X1802:32.768KHZ | F5503:1.1A/24V | X1801:24MHZ | X7601:27MHZ | PWB:51VP4 | MADE IN TAIWAN | 14291-1 | loveland-SKL MB | REV:A00
User.Comments: JOJO-1209 | MOJOJO | MARJ1 | ISMA-3
Ref Des/Silkscreen Top: X3101:25MHZ | X2401:32.768KHZ
User.17: 14959-1-T | 14960-1-T
User.28: ByImpedance:100.0@_REF_L1=("4.0/6.0(L1)" "3.5/5.0(L1)" "5.0/11.0(L1)")|_REF_L6=("4.0/6.0(L6)" "3.5/5.0(L6)" "5.0/11.0(L6)")|Type="DP"|_REF_L4=("4.0/9.0(L4)" "3.5/7.0(L4)")|_REF_L3=("4.0/9.0(L3)" "3.5/7.0(L3)")|imp="100.0" | ByImpedance:110.0@_REF_L1=("4.0/12.0(L1)")|_REF_L6=("4.0/12.0(L6)")|Type="DP"|_REF_L4=("3.5/13.0(L4)")|_REF_L3=("3.5/13.0(L3)")|imp="110.0" | ByImpedance:33.0@_REF_L1=("12.0(L1)")|_REF_L6=("12.0(L6)")|Type="SE"|_REF_L4=("12.5(L4)")|_REF_L3=("12.5(L3)")|imp="33.0" | ByImpedance:35.0@_REF_L1=("11.0(L1)")|_REF_L6=("11.0(L6)")|Type="SE"|_REF_L4=("10.5(L4)")|_REF_L3=("10.5(L3)")|imp="35.0" | ByImpedance:37.5@_REF_L1=("10.0(L1)")|_REF_L6=("10.0(L6)")|Type="SE"|_REF_L4=("9.5(L4)")|_REF_L3=("9.5(L3)")|imp="37.5" | ByImpedance:40.0@_REF_L1=("8.5(L1)")|_REF_L6=("8.5(L6)")|Type="SE"|_REF_L4=("8.0(L4)")|_REF_L3=("8.0(L3)")|imp="40.0" | ByImpedance:45.0@_REF_L1=("7.0(L1)")|_REF_L6=("7.0(L6)")|Type="SE"|_REF_L4=("6.5(L4)")|_REF_L3=("6.5(L3)")|imp="45.0" | ByImpedance:48.0@_REF_L1=("6.0(L1)")|_REF_L6=("6.0(L6)")|Type="SE"|_REF_L4=("5.5(L4)")|_REF_L3=("5.5(L3)")|imp="48.0" | ByImpedance:50.0@_REF_L1=("5.5(L1)" "5.5(L1)")|_REF_L6=("5.5(L6)" "5.5(L6)")|Type="SE"|_REF_L4=("5.0(L4)")|_REF_L3=("5.0(L3)")|imp="50.0" | ByImpedance:52.0@_REF_L1=("5.0(L1)")|_REF_L6=("5.0(L6)")|Type="SE"|_REF_L4=("4.5(L4)")|_REF_L3=("4.5(L3)")|imp="52.0" | ByImpedance:55.0@_REF_L1=("4.5(L1)")|_REF_L6=("4.5(L6)")|Type="SE"|_REF_L4=("4.0(L4)")|_REF_L3=("4.0(L3)")|imp="55.0" | ByImpedance:60.0@_REF_L1=("3.5(L1)")|_REF_L6=("3.5(L6)")|Type="SE"|_REF_L4=("nil(L4)")|_REF_L3=("nil(L3)")|imp="60.0" | ByImpedance:65.0@_REF_L1=("10.0/5.0(L1)")|_REF_L6=("10.0/5.0(L6)")|Type="DP"|_REF_L4=("9.0/5.0(L4)")|_REF_L3=("9.0/5.0(L3)")|imp="65.0" | ByImpedance:70.0@_REF_L1=("8.5/5.0(L1)")|_REF_L6=("8.5/5.0(L6)")|Type="DP"|_REF_L4=("8.0/5.0(L4)")|_REF_L3=("8.0/5.0(L3)")|imp="70.0" | ByImpedance:72.0@_REF_L1=("8.0/5.0(L1)")|_REF_L6=("8.0/5.0(L6)")|Type="DP"|_REF_L4=("7.0/5.0(L4)")|_REF_L3=("7.0/5.0(L3)")|imp="72.0" | ByImpedance:75.0@_REF_L1=("7.0/4.5(L1)")|_REF_L6=("7.0/4.5(L6)")|Type="DP"|_REF_L4=("7.0/6.0(L4)")|_REF_L3=("7.0/6.0(L3)")|imp="75.0" | ByImpedance:80.0@_REF_L1=("6.0/4.5(L1)")|_REF_L6=("6.0/4.5(L6)")|Type="DP"|_REF_L4=("5.5/5.0(L4)" "6.0/6.0(L4)" "5.0/4.0(L4)")|_REF_L3=("5.5/5.0(L3)" "6.0/6.0(L3)" "5.0/4.0(L3)")|imp="80.0" | ByImpedance:83.0@_REF_L1=("5.0/4.0(L1)")|_REF_L6=("5.0/4.0(L6)")|Type="DP"|_REF_L4=("4.5/4.0(L4)")|_REF_L3=("4.5/4.0(L3)")|imp="83.0" | ByImpedance:85.0@_REF_L1=("5.5/5.0(L1)" "5.0/4.5(L1)" "6.0/6.0(L1)")|_REF_L6=("5.5/5.0(L6)" "5.0/4.5(L6)" "6.0/6.0(L6)")|Type="DP"|_REF_L4=("5.5/7.0(L4)" "5.0/5.5(L4)" "4.5/4.5(L4)")|_REF_L3=("5.5/7.0(L3)" "5.0/5.5(L3)" "4.5/4.5(L3)")|imp="85.0" | ByImpedance:88.0@_REF_L1=("5.0/5.0(L1)" "4.5/4.0(L1)")|_REF_L6=("5.0/5.0(L6)" "4.5/4.0(L6)")|Type="DP"|_REF_L4=("4.0/4.5(L4)" "5.0/7.0(L4)")|_REF_L3=("4.0/4.5(L3)" "5.0/7.0(L3)")|imp="88.0" | ByImpedance:90.0@_REF_L1=("4.0/4.0(L1)" "5.0/6.0(L1)")|_REF_L6=("4.0/4.0(L6)" "5.0/6.0(L6)")|Type="DP"|_REF_L4=("5.0/8.0(L4)" "4.0/5.0(L4)" "4.5/6.0(L4)")|_REF_L3=("5.0/8.0(L3)" "4.0/5.0(L3)" "4.5/6.0(L3)")|imp="90.0" | ByImpedance:93.0@_REF_L1=("4.0/4.5(L1)" "5.0/6.5(L1)")|_REF_L6=("4.0/4.5(L6)" "5.0/6.5(L6)")|Type="DP"|_REF_L4=("4.0/6.0(L4)")|_REF_L3=("4.0/6.0(L3)")|imp="93.0" | ByImpedance:95.0@_REF_L1=("4.5/6.0(L1)")|_REF_L6=("4.5/6.0(L6)")|Type="DP"|_REF_L4=("4.0/6.5(L4)")|_REF_L3=("4.0/6.5(L3)")|imp="95.0" | LayerIndex:nil | Source:6-1.2-3k.xls | artWorks:("_REF_L3" "_REF_L4" "_REF_L6" "_REF_L1") | gtImpOutlineUsed:BOARD GEOMETRY/PANEL_OUTLINE
User.30: Board Accuracy Check,Jun 05 17:16:16 2015,Passed | Component Overlap Check,Jan 08 13:06:42 2015,97 errors | Dummy-Static-No Shape On Layer Check,Jun 05 17:16:17 2015,Passed | Split Plane Check,Feb 12 16:21:59 2015,Passed
User.33: This gerber is just for your reference to find the DP impedance traces in layer L1. | DP IMPEDANCE TABLE: L1 | * - Denotes that this Impedance | is NOT used | IMP(Ohm) | *65.0 | *70.0 | *72.0 | *75.0 | 80.0 | *83.0 | *85.0 | 85.0 | *88.0 | *90.0 | *93.0 | *95.0 | *100.0 | 100.0 | *110.0 | WIDTH(mils) | 10.0/5.0 | 8.5/5.0 | 8.0/5.0 | 7.0/4.5 | 6.0/4.5 | 5.0/4.0 | 5.5/5.0 | 5.0/4.5 | 6.0/6.0 | 5.0/5.0 | 4.5/4.0 | 4.0/4.0 | 5.0/6.0 | 4.0/4.5 | 5.0/6.5 | 4.5/6.0 | 4.0/6.0 | 3.5/5.0 | 5.0/11.0 | 4.0/12.0 | TYPE | DP
User.35: This gerber is just for your reference to find the SE impedance traces in layer L1. | SE IMPEDANCE TABLE: L1 | * - Denotes that this Impedance | is NOT used | IMP(Ohm) | *33.0 | *35.0 | *37.5 | 40.0 | 45.0 | *48.0 | 50.0 | *52.0 | *55.0 | *60.0 | WIDTH(mils) | 12.0 | 11.0 | 10.0 | 8.5 | 7.0 | 6.0 | 5.5 | 5.0 | 4.5 | 3.5 | TYPE | SE
User.37: This gerber is just for your reference to find the DP impedance traces in layer L3. | DP IMPEDANCE TABLE: L3 | * - Denotes that this Impedance | is NOT used | IMP(Ohm) | *65.0 | *70.0 | *72.0 | *75.0 | *80.0 | 80.0 | 83.0 | *85.0 | 85.0 | *88.0 | *90.0 | *93.0 | *95.0 | *100.0 | *110.0 | WIDTH(mils) | 9.0/5.0 | 8.0/5.0 | 7.0/5.0 | 7.0/6.0 | 5.5/5.0 | 6.0/6.0 | 5.0/4.0 | 4.5/4.0 | 5.5/7.0 | 5.0/5.5 | 4.5/4.5 | 4.0/4.5 | 5.0/7.0 | 5.0/8.0 | 4.0/5.0 | 4.5/6.0 | 4.0/6.0 | 4.0/6.5 | 4.0/9.0 | 3.5/7.0 | 3.5/13.0 | TYPE | DP
User.39: This gerber is just for your reference to find the SE impedance traces in layer L3. | SE IMPEDANCE TABLE: L3 | * - Denotes that this Impedance | is NOT used | IMP(Ohm) | *33.0 | *35.0 | *37.5 | 40.0 | 45.0 | *48.0 | 50.0 | *52.0 | *55.0 | *60.0 | WIDTH(mils) | 12.5 | 10.5 | 9.5 | 8.0 | 6.5 | 5.5 | 5.0 | 4.5 | 4.0 | nil | TYPE | SE
User.41: This gerber is just for your reference to find the DP impedance traces in layer L4. | DP IMPEDANCE TABLE: L4 | * - Denotes that this Impedance | is NOT used | IMP(Ohm) | *65.0 | *70.0 | *72.0 | *75.0 | *80.0 | 80.0 | 83.0 | *85.0 | 85.0 | *88.0 | *90.0 | *93.0 | *95.0 | *100.0 | *110.0 | WIDTH(mils) | 9.0/5.0 | 8.0/5.0 | 7.0/5.0 | 7.0/6.0 | 5.5/5.0 | 6.0/6.0 | 5.0/4.0 | 4.5/4.0 | 5.5/7.0 | 5.0/5.5 | 4.5/4.5 | 4.0/4.5 | 5.0/7.0 | 5.0/8.0 | 4.0/5.0 | 4.5/6.0 | 4.0/6.0 | 4.0/6.5 | 4.0/9.0 | 3.5/7.0 | 3.5/13.0 | TYPE | DP
User.43: This gerber is just for your reference to find the SE impedance traces in layer L4. | SE IMPEDANCE TABLE: L4 | * - Denotes that this Impedance | is NOT used | IMP(Ohm) | *33.0 | *35.0 | *37.5 | 40.0 | 45.0 | *48.0 | 50.0 | *52.0 | *55.0 | *60.0 | WIDTH(mils) | 12.5 | 10.5 | 9.5 | 8.0 | 6.5 | 5.5 | 5.0 | 4.5 | 4.0 | nil | TYPE | SE
User.45: AUD_AGND | GND | DCBATOUT | +VCCSA | VGA_CORE | Note:Refer to DRILL layer for ELLIPSE drill direction | FIGURE | SIZE | 10.0 | 16.0 | 21.0 | 28.0 | 36.0 | 48.0 | 115.0 | 117.0 | 126.0 | 166.0 | 182.0 | 44.0 | 46.0 | 63.0 | 65.0 | 86.0 | 158.0 | 56.0x26.0 | 60.0x36.0 | 71.0x36.0 | 90.0x28.0 | 95.0x28.0 | 110.0x40.0 | 162.0x130.0 | 237.0x56.0 | DRILL CHART: TOP to BOTTOM | ALL UNITS ARE IN MILS | PLATED | NON-PLATED | QTY | 4044 | 1174 | 19 | 18 | 8 | 4 | 3 | 2 | 1 | 5 | 7 | This gerber is just for your reference to find the DP impedance traces in layer L6. | This gerber is just for your reference to find the SE impedance traces in layer L6. | DP IMPEDANCE TABLE: L6 | SE IMPEDANCE TABLE: L6 | * - Denotes that this Impedance | is NOT used | Model | Loveland-SKL MB | PCB_NO | 14291 | VER. | Layer | DRILL | L1 | L2VCC | L3 | TMASK | TPLACE | TSILK | TSMD | Designer | MOSSE | Date | 09/18/2015 | IMP(Ohm) | *33.0 | *65.0 | *35.0 | *70.0 | *37.5 | *72.0 | *75.0 | 40.0 | 45.0 | 80.0 | *48.0 | 83.0 | *85.0 | 50.0 | 85.0 | *52.0 | *55.0 | *88.0 | *60.0 | *90.0 | *93.0 | *95.0 | *100.0 | 100.0 | *110.0 | WIDTH(mils) | 12.0 | 11.0 | 8.5 | 7.0 | 6.0 | 5.5 | 5.0 | 4.5 | 3.5 | 10.0/5.0 | 8.5/5.0 | 8.0/5.0 | 7.0/4.5 | 6.0/4.5 | 5.0/4.0 | 5.5/5.0 | 5.0/4.5 | 6.0/6.0 | 5.0/5.0 | 4.5/4.0 | 4.0/4.0 | 5.0/6.0 | 4.0/4.5 | 5.0/6.5 | 4.5/6.0 | 4.0/6.0 | 3.5/5.0 | 5.0/11.0 | 4.0/12.0 | TYPE | SE | DP | BMASK | BPLACE | BSILK | BSMD | L4 | L5GND | L6
